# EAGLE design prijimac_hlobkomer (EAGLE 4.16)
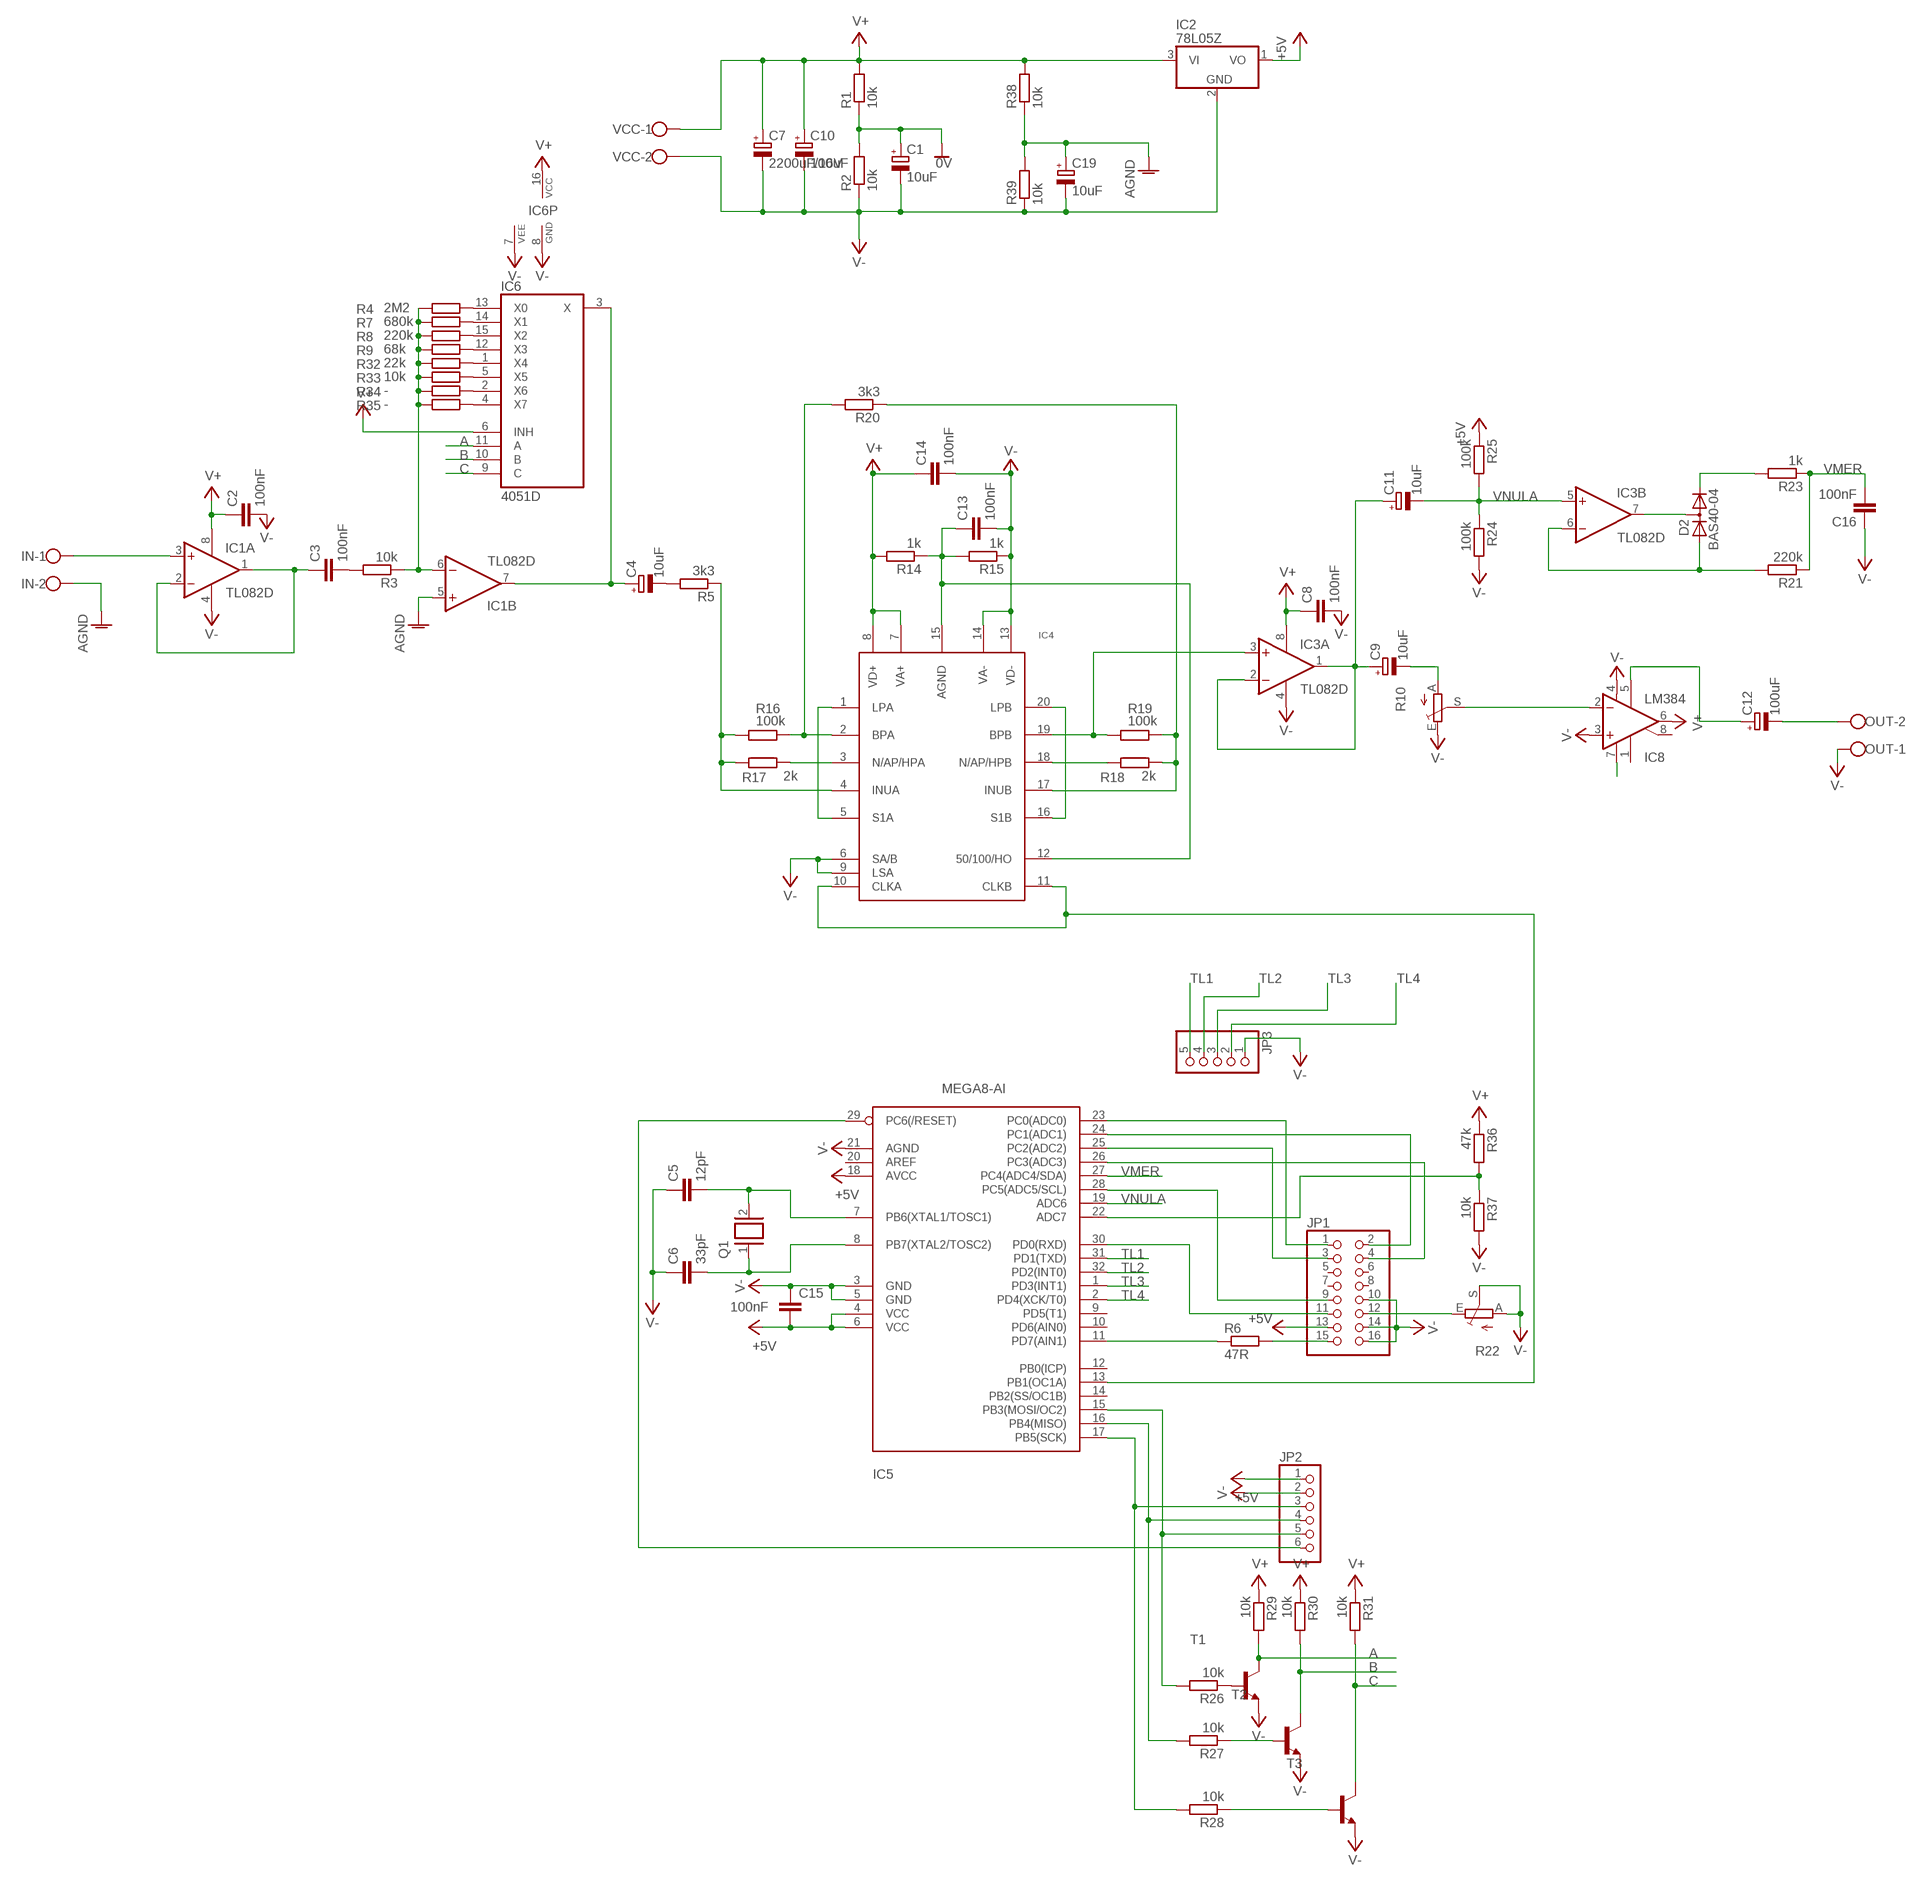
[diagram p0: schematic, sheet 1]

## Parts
C1  10uF  CPOL-EUE2.5-5  [E2,5-5]
C2  100nF  C-EUC0805K  [C0805K]
C3  100nF  C-EUC0805K  [C0805K]
C4  10uF  CPOL-EUE2.5-5  [E2,5-5]
C5  12pF  C-EUC0805K  [C0805K]
C6  33pF  C-EUC0805K  [C0805K]
C7  2200uF/16V  CPOL-EUE5-13  [E5-13]
C8  100nF  C-EUC0805K  [C0805K]
C9  10uF  CPOL-EUE2.5-5  [E2,5-5]
C10  100uF  CPOL-EUE2.5-5  [E2,5-5]
C11  10uF  CPOL-EUE2.5-5  [E2,5-5]
C12  100uF  CPOL-EUE2.5-5  [E2,5-5]
C13  100nF  C-EUC0805K  [C0805K]
C14  100nF  C-EUC0805K  [C0805K]
C15  100nF  C-EUC0805K  [C0805K]
C16  100nF  C-EUC0805K  [C0805K]
C19  10uF  CPOL-EUE2.5-5  [E2,5-5]
D2  BAS40-04  BAV199  [SOT23]
IC1  TL082D  [SO08]
IC2  78L05Z  [TO92]
IC3  TL082D  [SO08]
IC4  LTC1060DIL  [DIL20]
IC5  MEGA8-AI  [TQFP32-08]
IC6  4051D  [SO16]
IC8  LM384  NE5534N  [DIL08]
IN  W237-102  [W237-102]
JP1  PINHD-2X8  [2X08]
JP2  PINHD-1X6  [1X06]
JP3  PINHD-1X5  [1X05]
OUT  W237-102  [W237-102]
Q1  XTAL/S  [QS]
R1  10k  R-EU_R0805  [R0805]
R2  10k  R-EU_R0805  [R0805]
R3  10k  R-EU_R0805  [R0805]
R4  2M2  R-EU_R0805  [R0805]
R5  3k3  R-EU_R0805  [R0805]
R6  47R  R-EU_0207/7  [0207/7]
R7  680k  R-EU_R0805  [R0805]
R8  220k  R-EU_R0805  [R0805]
R9  68k  R-EU_R0805  [R0805]
R10  TRIM_EU-S64W  [S64W]
R14  1k  R-EU_R0805  [R0805]
R15  1k  R-EU_R0805  [R0805]
R16  100k  R-EU_R0805  [R0805]
R17  2k  R-EU_R0805  [R0805]
R18  2k  R-EU_R0805  [R0805]
R19  100k  R-EU_R0805  [R0805]
R20  3k3  R-EU_R0805  [R0805]
R21  220k  R-EU_R0805  [R0805]
R22  TRIM_EU-CA6V  [CA6V]
R23  1k  R-EU_R0805  [R0805]
R24  100k  R-EU_R0805  [R0805]
R25  100k  R-EU_R0805  [R0805]
R26  10k  R-EU_R0805  [R0805]
R27  10k  R-EU_R0805  [R0805]
R28  10k  R-EU_R0805  [R0805]
R29  10k  R-EU_R0805  [R0805]
R30  10k  R-EU_R0805  [R0805]
R31  10k  R-EU_R0805  [R0805]
R32  22k  R-EU_R0805  [R0805]
R33  10k  R-EU_R0805  [R0805]
R34  -  R-EU_R0805  [R0805]
R35  -  R-EU_R0805  [R0805]
R36  47k  R-EU_R0805  [R0805]
R37  10k  R-EU_R0805  [R0805]
R38  10k  R-EU_R0805  [R0805]
R39  10k  R-EU_R0805  [R0805]
T1  BC817-40-NPN-SOT23-BEC  [SOT23-BEC]
T2  BC817-40-NPN-SOT23-BEC  [SOT23-BEC]
T3  BC817-40-NPN-SOT23-BEC  [SOT23-BEC]
VCC  W237-102  [W237-102]

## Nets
0V: C1.+ R1.1 R2.2
+5V: C15.1 IC2.1(VO) IC5.4(VCC) IC5.6(VCC) IC5.18(AVCC) JP1.13 JP2.1 R25.1
A: IC6.11(A) R29.2 T1.C
AGND: C19.+ IC1.5(B:+IN) IN.2 R38.1 R39.2
B: IC6.10(B) R30.2 T2.C
B$1-0: IC5.23(PC0(ADC0)) JP1.1
B$1-1: IC5.24(PC1(ADC1)) JP1.2
B$1-2: IC5.25(PC2(ADC2)) JP1.3
B$1-3: IC5.26(PC3(ADC3)) JP1.4
C: IC6.9(C) R31.2 T3.C
N$1: C3.2 R3.2
N$2: C4.- R5.2
N$3: C6.2 IC5.8(PB7(XTAL2/TOSC2)) Q1.1
N$4: C3.1 IC1.1(A:OUT) IC1.2(A:-IN)
N$5: C5.2 IC5.7(PB6(XTAL1/TOSC1)) Q1.2
N$6: IC6.13(X0) R4.1
N$7: IC1.6(B:-IN) R3.1 R4.2 R7.2 R8.2 R9.2 R32.2 R33.2 R34.2 R35.2
N$8: C4.+ IC1.7(B:OUT) IC6.3(X)
N$9: IC6.14(X1) R7.1
N$10: IC5.30(PD0(RXD)) JP1.11
N$11: IC1.3(A:+IN) IN.1
N$12: IC6.15(X2) R8.1
N$13: C13.1 IC4.12(50/100/HO) IC4.15(AGND) R14.1 R15.2
N$14: C9.+ C11.+ IC3.1(A:OUT) IC3.2(A:-IN)
N$15: C9.- R10.A
N$16: IC8.7(V+)
N$18: IC8.2(-IN) R10.S
N$19: C12.+ IC8.5(CMP)
N$21: C12.- OUT.2
N$22: IC6.12(X3) R9.1
N$23: IC4.1(LPA) IC4.5(S1A)
N$24: IC4.16(S1B) IC4.20(LPB)
N$25: IC4.4(INUA) R5.1 R16.2 R17.2
N$26: IC4.3(N/AP/HPA) R17.1
N$27: IC4.2(BPA) R16.1 R20.2
N$28: IC3.3(A:+IN) IC4.19(BPB) R19.2
N$29: IC4.18(N/AP/HPB) R18.2
N$30: IC4.17(INUB) R18.1 R19.1 R20.1
N$31: JP1.15 R6.2
N$32: IC5.11(PD7(AIN1)) R6.1
N$33: IC4.10(CLKA) IC4.11(CLKB) IC5.13(PB1(OC1A))
N$34: IC5.28(PC5(ADC5/SCL)) JP1.9
N$35: IC5.29(PC6(/RESET)) JP2.6
N$36: IC5.17(PB5(SCK)) JP2.3 R28.2
N$37: IC5.16(PB4(MISO)) JP2.4 R27.2
N$38: IC5.15(PB3(MOSI/OC2)) JP2.5 R26.2
N$39: D2.3(AC) IC3.7(B:OUT)
N$40: D2.1(A) IC3.6(B:-IN) R21.2
N$41: IC5.22(ADC7) R36.2 R37.1
N$42: JP1.12 R22.E
N$43: D2.2(C) R23.2
N$45: R26.1 T1.B
N$46: R27.1 T2.B
N$47: R28.1 T3.B
N$51: IC6.1(X4) R32.1
N$52: IC6.5(X5) R33.1
N$53: IC6.2(X6) R34.1
N$54: IC6.4(X7) R35.1
TL1: IC5.31(PD1(TXD)) JP3.5
TL2: IC5.32(PD2(INT0)) JP3.4
TL3: IC5.1(PD3(INT1)) JP3.3
TL4: IC5.2(PD4(XCK/T0)) JP3.2
V+: C2.1 C7.+ C8.1 C10.+ C14.1 IC1.8(P:V+) IC2.3(VI) IC3.8(P:V+) IC4.7(VA+) IC4.8(VD+) IC6.6(INH) IC6.16(VCC) IC8.6(OUT) R1.2 R14.2 R29.1 R30.1 R31.1 R36.1 R38.2 VCC.1
V-: C1.- C2.2 C5.1 C6.1 C7.- C8.2 C10.- C13.2 C14.2 C15.2 C16.1 C19.- IC1.4(P:V-) IC2.2(GND) IC3.4(P:V-) IC4.6(SA/B) IC4.9(LSA) IC4.13(VD-) IC4.14(VA-) IC5.3(GND) IC5.5(GND) IC5.21(AGND) IC6.7(VEE) IC6.8(GND) IC8.3(+IN) IC8.4(V-) JP1.10 JP1.14 JP1.16 JP2.2 JP3.1 OUT.1 R2.1 R10.E R15.1 R22.A R22.S R24.2 R37.2 R39.1 T1.E T2.E T3.E VCC.2
VMER: C16.2 IC5.27(PC4(ADC4/SDA)) R21.1 R23.1
VNULA: C11.- IC3.5(B:+IN) IC5.19(ADC6) R24.1 R25.2
Unconnected: IC5.9(PD5(T1)) IC5.10(PD6(AIN0)) IC5.12(PB0(ICP)) IC5.14(PB2(SS/OC1B)) IC5.20(AREF) IC8.1(ON) IC8.8(ON/CMP) JP1.5 JP1.6 JP1.7 JP1.8

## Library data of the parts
C1 C4 C7 C9-C12 C19 = rcl:CPOL-EU: POLARIZED CAPACITOR, European symbol
C2 C3 C5 C6 C8 C13-C16 = rcl:C-EU: CAPACITOR, European symbol
D2 = diode:BAV199: DIODE low-leakage double diode
IC1 IC3 = linear:TL082: OP AMP
IC2 = linear:78*: Positive VOLTAGE REGULATOR Source: http://cache.national.com/ds/LM/LM78L05.pdf http://www.fairchildsemi.com/ds/LM/LM7805.pdf
IC4 = moje:LTC1060
IC5 = atmel:MEGA8: MICROCONTROLLER 8 Kbytes FLASH 1 kbytes SRAM 512 bytes EEPROM USART 6-channel 10 bit ADC 2-channel 8 bit ADC
IC6 = 40xx:4051: 8-channel ANALOG MULTIPLEXER
IC8 = linear:NE5534: AUDIO AMPLIFIER
IN OUT VCC = con-wago-500:W237-102: WAGO SCREW CLAMP
JP1 = pinhead:PINHD-2X8: PIN HEADER
JP2 = pinhead:PINHD-1X6: PIN HEADER
JP3 = pinhead:PINHD-1X5: PIN HEADER
Q1 = special:XTAL/S: CRYSTAL
R1-R9 R14-R21 R23-R39 = rcl:R-EU_: RESISTOR, European symbol
R10 R22 = pot:TRIM_EU-: POTENTIOMETER
T1-T3 = transistor:*-NPN-: NPN Transistror

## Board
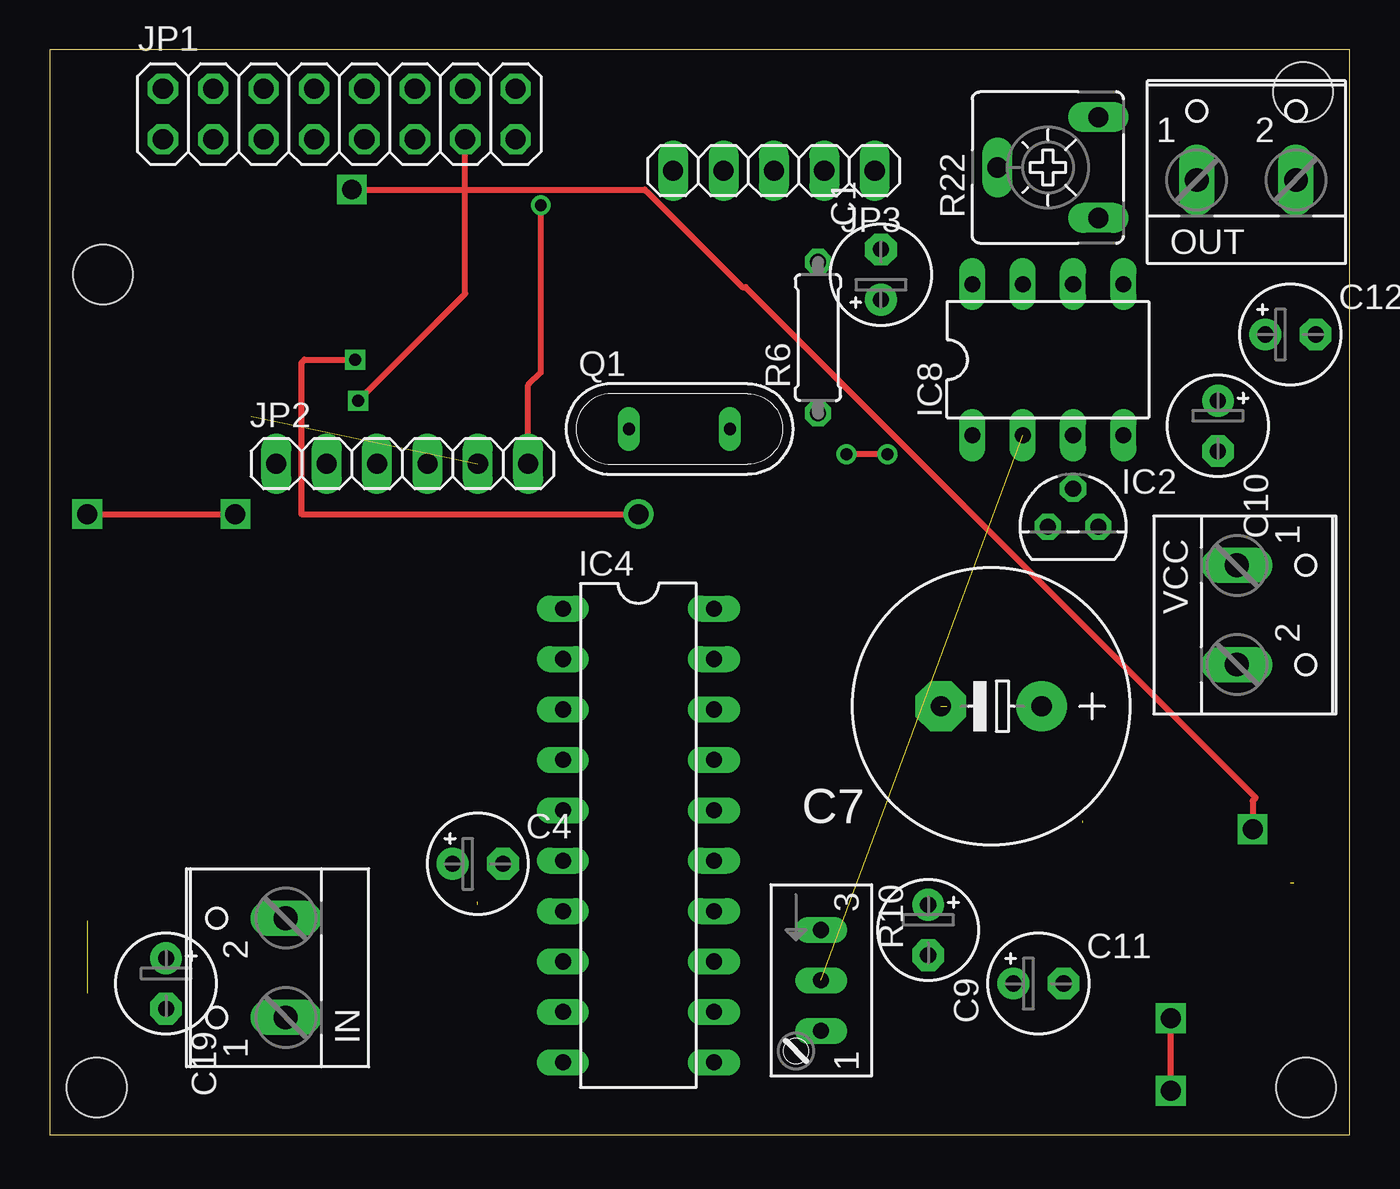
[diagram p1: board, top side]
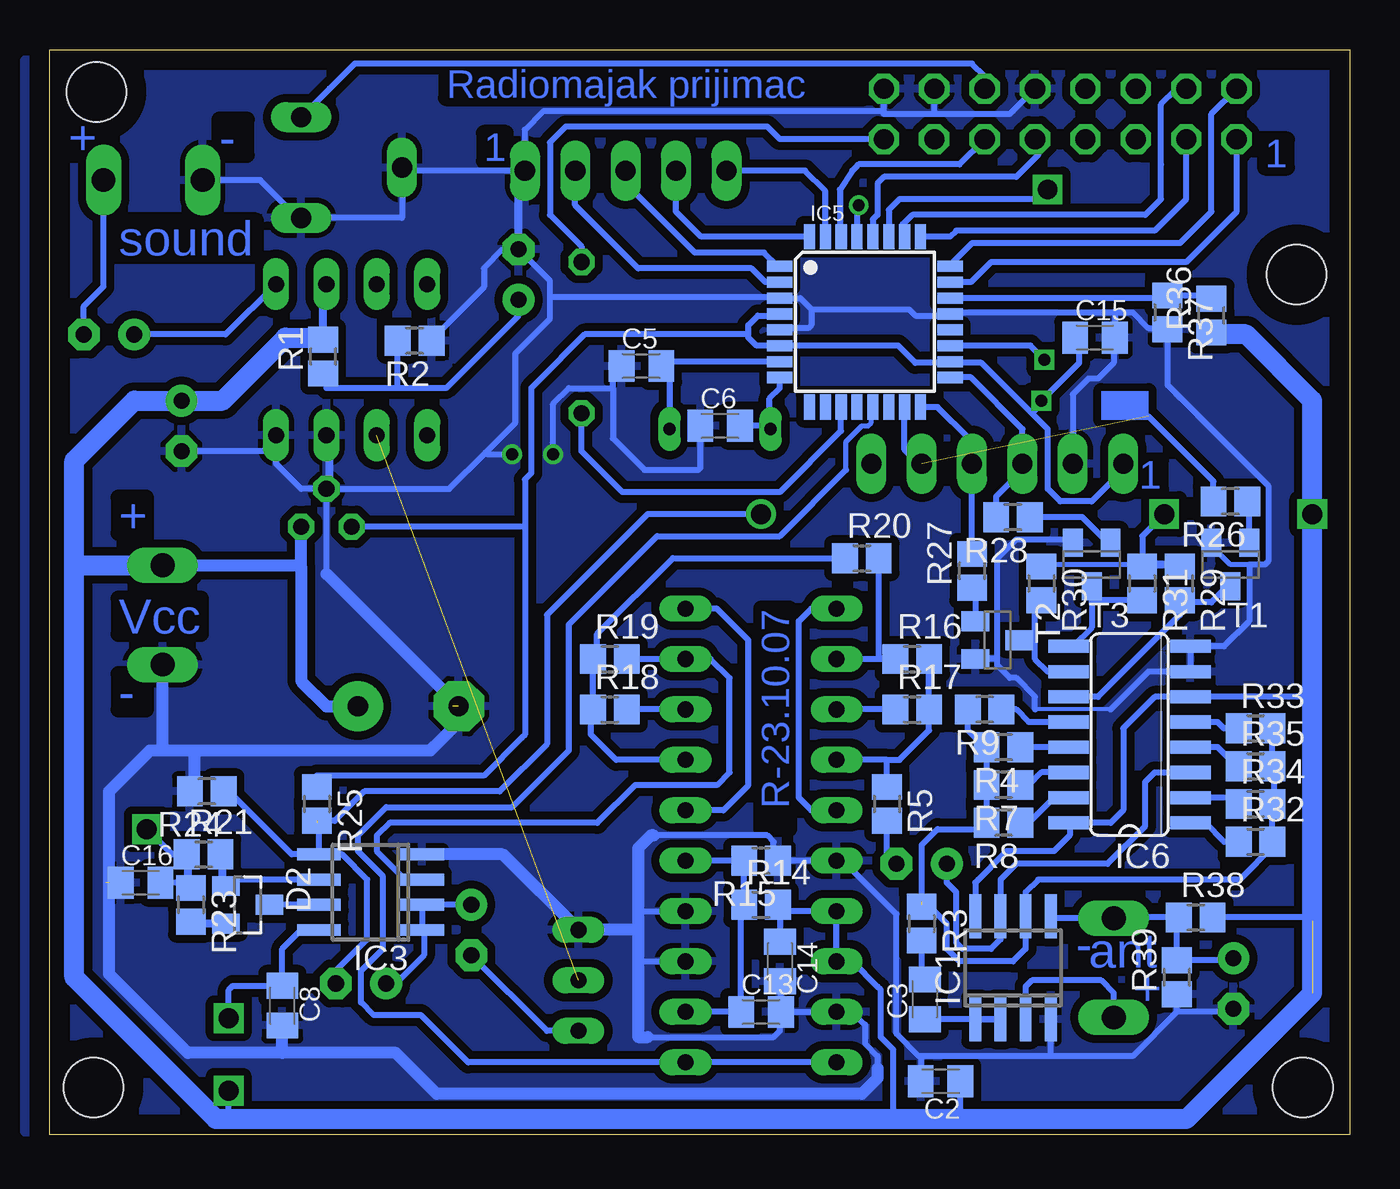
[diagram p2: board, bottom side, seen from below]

Size 65.54 x 54.67 mm. Coordinates in mm from the lower left corner, seen from the top.
Outline: 0,0 65.54,0 65.54,54.67 0,54.67 0,0
Copper layers (1*16): Top 0.035mm / dielectric 1.5mm / Bottom 0.035mm
Design rules "default": minimum track width 10mil, minimum drill 24mil, track to track 8mil, track to pad 8mil, pad to pad 8mil, via to via 8mil, smd to smd 8mil, copper to edge 40mil, drill to drill 8mil, minimum pad ring 10mil, minimum via ring 8mil, stop-mask expansion 4mil, vias tented up to drill 0mil, thermal gap 10mil
Holes 3 mm at 2.69,43.33 2.38,2.38 63.34,2.38 63.18,52.54

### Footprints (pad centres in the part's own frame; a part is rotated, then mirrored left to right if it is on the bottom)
E2,5-5 = drill 0.813 pad 1.6 round: + -1.27,0 | drill 0.813 pad 1.6 octagon: - 1.27,0
C0805K = smd 1.3 x 1.6: 1 -1,0; 2 1,0
E5-13 = drill 1.016 pad 2.54 round: + -2.54,0 | drill 1.016 pad 2.54 octagon: - 2.54,0
SOT23 = smd 1 x 1.4: 1 -0.95,-1.1; 2 0.95,-1.1; 3 0,1.1
SO08 = smd 0.6 x 2.2: 1 -1.905,-2.6; 2 -0.635,-2.6; 3 0.635,-2.6; 4 1.905,-2.6; 5 1.905,2.6; 6 0.635,2.6; 7 -0.635,2.6; 8 -1.905,2.6
TO92 = drill 0.813 octagon: 1 -1.27,0; 2 0,1.905; 3 1.27,0
DIL20 = drill 0.813 long: 1 -11.43,-3.81; 2 -8.89,-3.81; 3 -6.35,-3.81; 4 -3.81,-3.81; 5 -1.27,-3.81; 6 1.27,-3.81; 7 3.81,-3.81; 8 6.35,-3.81; 9 8.89,-3.81; 10 11.43,-3.81; 11 11.43,3.81; 12 8.89,3.81; 13 6.35,3.81; 14 3.81,3.81; 15 1.27,3.81; 16 -1.27,3.81; 17 -3.81,3.81; 18 -6.35,3.81; 19 -8.89,3.81; 20 -11.43,3.81
TQFP32-08 = smd 1.27 x 0.559: 1 -4.293,2.8; 2 -4.293,2; 3 -4.293,1.2; 4 -4.293,0.4; 5 -4.293,-0.4; 6 -4.293,-1.2; 7 -4.293,-2; 8 -4.293,-2.8; 17 4.293,-2.8; 18 4.293,-2; 19 4.293,-1.2; 20 4.293,-0.4; 21 4.293,0.4; 22 4.293,1.2; 23 4.293,2; 24 4.293,2.8 | smd 0.559 x 1.27: 9 -2.8,-4.293; 10 -2,-4.293; 11 -1.2,-4.293; 12 -0.4,-4.293; 13 0.4,-4.293; 14 1.2,-4.293; 15 2,-4.293; 16 2.8,-4.293; 25 2.8,4.293; 26 2,4.293; 27 1.2,4.293; 28 0.4,4.293; 29 -0.4,4.293; 30 -1.2,4.293; 31 -2,4.293; 32 -2.8,4.293
SO16 = smd 0.66 x 2.032: 1 -4.445,-3.073; 2 -3.175,-3.073; 3 -1.905,-3.073; 4 -0.635,-3.073; 5 0.635,-3.073; 6 1.905,-3.073; 7 3.175,-3.073; 8 4.445,-3.073; 9 4.445,3.073; 10 3.175,3.073; 11 1.905,3.073; 12 0.635,3.073; 13 -0.635,3.073; 14 -1.905,3.073; 15 -3.175,3.073; 16 -4.445,3.073
DIL08 = drill 0.813 long: 1 -3.81,-3.81; 2 -1.27,-3.81; 3 1.27,-3.81; 4 3.81,-3.81; 5 3.81,3.81; 6 1.27,3.81; 7 -1.27,3.81; 8 -3.81,3.81
W237-102 = drill 1.194 long: 1 -2.5,-1.27; 2 2.5,-1.27
2X08 = drill 1.016 octagon: 1 -8.89,-1.27; 2 -8.89,1.27; 3 -6.35,-1.27; 4 -6.35,1.27; 5 -3.81,-1.27; 6 -3.81,1.27; 7 -1.27,-1.27; 8 -1.27,1.27; 9 1.27,-1.27; 10 1.27,1.27; 11 3.81,-1.27; 12 3.81,1.27; 13 6.35,-1.27; 14 6.35,1.27; 15 8.89,-1.27; 16 8.89,1.27
1X06 = drill 1.016 long: 1 -6.35,0; 2 -3.81,0; 3 -1.27,0; 4 1.27,0; 5 3.81,0; 6 6.35,0
1X05 = drill 1.016 long: 1 -5.08,0; 2 -2.54,0; 3 0,0; 4 2.54,0; 5 5.08,0
QS = drill 0.61 long: 1 -2.54,0; 2 2.54,0
R0805 = smd 1.3 x 1.5: 1 -0.85,0; 2 0.85,0
0207/7 = drill 0.813 octagon: 1 -3.81,0; 2 3.81,0
S64W = drill 0.813 long: A 2.54,1.27; E -2.54,1.27; S 0,1.27
CA6V = drill 1.016 long: A -2.54,-2.54; E 2.54,-2.54; S 0,2.54
SOT23-BEC = smd 1 x 1.4: B -0.95,-1.1; C 0,1.1; E 0.95,-1.1

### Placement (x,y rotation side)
C1  41.9,43.33 90 top
C2  20.63,2.69 180 bottom
C3  21.43,6.82 90 bottom
C4  21.58,13.65 0 top
C5  35.71,38.73 0 bottom
C6  31.74,35.71 0 bottom
C7  47.46,21.59 180 top
C8  53.81,6.5 270 bottom
C9  44.29,10.31 270 top
C10  58.89,35.71 270 top
C11  49.84,7.61 0 top
C12  62.54,40.32 0 top
C13  29.68,6.19 0 bottom
C14  28.73,8.73 270 bottom
C15  12.85,40.16 0 bottom
C16  60.95,12.69 0 bottom
C19  5.87,7.61 270 top
D2  55.56,11.58 270 bottom
IC1  16.98,8.41 0 bottom
IC2  51.59,30.63 0 top
IC3  49.37,12.22 90 bottom
IC4  29.68,15.08 270 top
IC5  24.44,40.95 0 bottom
IC6  11.11,20.16 90 bottom
IC8  50.32,39.05 0 top
IN  10.63,8.41 90 top
JP1  14.6,51.43 0 top
JP2  17.77,33.81 0 top
JP3  36.51,48.57 180 top
OUT  60.32,49.37 0 top
Q1  31.74,35.56 0 top
R1  51.75,39.21 90 bottom
R2  47.14,40 180 bottom
R3  21.58,10.63 270 bottom
R4  17.46,19.52 180 bottom
R5  23.33,16.66 270 bottom
R6  38.73,40.16 90 top
R7  17.46,17.62 180 bottom
R8  17.46,15.71 180 bottom
R9  18.41,21.43 180 bottom
R10  37.62,7.77 270 top
R14  29.68,11.58 0 bottom
R15  29.68,13.81 180 bottom
R16  22.06,23.97 0 bottom
R17  22.06,21.43 0 bottom
R18  37.3,21.43 0 bottom
R19  37.3,23.97 0 bottom
R20  24.6,29.05 0 bottom
R21  57.78,14.12 0 bottom
R22  50.32,48.73 90 top
R23  58.41,11.58 270 bottom
R24  57.62,17.3 180 bottom
R25  52.06,16.66 270 bottom
R26  6.03,31.9 180 bottom
R27  19.04,28.41 90 bottom
R28  16.98,31.11 180 bottom
R29  8.57,27.78 270 bottom
R30  15.55,27.78 270 bottom
R31  10.47,27.78 270 bottom
R32  4.76,14.76 0 bottom
R33  4.76,20.47 0 bottom
R34  4.76,16.66 0 bottom
R35  4.76,18.57 0 bottom
R36  6.98,41.27 90 bottom
R37  9.2,41.43 270 bottom
R38  7.77,10.95 0 bottom
R39  8.73,7.93 90 bottom
T1  6.03,28.73 180 bottom
T2  17.77,24.92 270 bottom
T3  13.01,28.73 180 bottom
VCC  61.11,26.19 270 top

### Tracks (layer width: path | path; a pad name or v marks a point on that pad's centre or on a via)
0V
  Bottom 0.305: C1.+ 41.9,41.27 45.55,37.62 48.09,37.62 | 48.09,37.62 51.59,37.62 51.59,38.25 51.75,38.41 R1.1 | R2.2 47.99,37.72 48.09,37.62
+5V  (via drill 0.6)
  Top 0.305: JP1.13 20.95,42.38 v15.55,36.98
  Bottom 0.305: 20.31,38.89 21.9,38.89 22.77,39.75 28.66,39.75 28.73,39.68 28.73,39.69 IC5.6 29.91,39.75 30.32,40.16 30.32,40.32 | JP2.1 11.42,33.49 13.01,31.9 14.6,31.9 15.23,32.54 15.23,35.56 16.03,36.35 | 16.03,36.35 18.57,38.89 20.31,38.89 | 20.31,38.89 20.25,38.95 IC5.18 | R25.1 52.06,17.3 52.06,18.09 43.65,18.09 41.74,20 | 41.74,20 | 41.74,20 41.59,20.16 41.59,30.63 | 41.59,30.63 IC2.1 | 41.59,30.63 | 40.95,37.94 38.57,40.32 30.32,40.32 | 16.03,36.35 15.55,36.83 v15.55,36.98 13.65,38.89 13.65,40 13.81,40.16 C15.1 | 30.32,40.32 30.32,40.79 29.84,41.27 28.73,41.27 28.73,41.28 IC5.4 | 30.32,40.32 | 41.59,30.63 41.59,33.02 41.27,33.33 41.27,37.62 40.95,37.94 | 40.95,37.94
A
  Bottom 0.305: IC6.11 12.69,22.06 8.57,26.19 8.57,26.82 | 8.57,27.14 R29.2 8.57,26.82 | T1.C 6.17,27.63 6.98,26.82 8.57,26.82
AGND
  Bottom 0.305: 15.08,10.95 15.04,10.91 | C19.+ 5.97,8.78 R39.2 8.73,10.79 8.57,10.95 R38.1 11.9,10.95 IN.2 15.04,10.91 | 15.08,10.95 IC1.5 | 15.04,10.91 15.08,10.95
B
  Bottom 0.305: IC6.10 15.23,23.33 15.87,23.97 15.87,24.92 | R30.2 15.77,26.93 15.87,26.82 15.87,24.92 | 15.87,24.92 T2.C
B$1-0
  Bottom 0.305: IC5.23 19.11,42.95 18.09,43.97 8.25,43.97 5.71,46.51 5.71,49.68 5.87,49.84 5.71,50 JP1.1
B$1-1
  Bottom 0.305: JP1.2 6.98,51.43 6.98,46.51 8.57,44.92 19.04,44.92 20.16,43.81 20.15,43.8 IC5.24
B$1-2
  Bottom 0.305: IC5.25 20.15,45.25 19.84,45.56 9.84,45.56 8.25,47.14 8.25,50 8.41,50.16 JP1.3
B$1-3
  Bottom 0.305: JP1.4 8.73,52.7 9.52,51.91 9.52,48.89 | 10.31,46.35 22.06,46.35 22.54,45.87 22.54,45.24 22.53,45.25 IC5.26 | 10.31,46.35 | 10.31,46.35 9.52,47.14 9.52,48.89 | 9.52,48.89
C
  Bottom 0.305: IC6.9 13.96,24.6 13.01,25.55 13.01,26.82 | 13.01,26.82 T3.C | R31.2 12.91,26.93 13.01,26.82
N$1
  Bottom 0.305: 21.43,10 R3.2 21.58,8.09 21.43,7.93 C3.2
N$2
  Bottom 0.305: C4.- | R5.2 23.33,14.12 C4.-
N$3
  Bottom 0.305: 29.2,35.71 29.2,36.35 29.25,36.4 29.25,37.1 28.73,37.62 28.73,38.1 IC5.8 | Q1.1 29.2,35.71 | C6.2 29.2,35.71
N$4
  Bottom 0.305: IC1.1 18.89,5.87 18.82,5.81 IC1.2 21.37,5.81 21.43,5.87 C3.1
N$5
  Bottom 0.305: IC5.7 34.54,38.95 34.71,38.78 C5.2 34.44,38.73 34.28,38.89 Q1.2
N$6
  Bottom 0.305: IC6.13 R4.1
N$7  (1 unrouted)
  Bottom 0.305: R4.2 18.09,19.52 18.31,19.74 | R4.2 18.31,17.72 18.41,17.62 R7.2 18.31,15.61 | 18.31,15.61 R8.2 | 18.31,15.61 18.09,15.39 20.79,15.39 21.58,14.6 21.58,11.74 | 3.8,18.57 R35.2 | R33.2 3.91,18.67 3.8,18.57 | 3.8,18.57 3.8,16.66 R34.2 3.91,14.86 3.8,14.76 | 3.8,14.76 R32.2 4.12,14.76 | R4.2 18.41,19.52 19.26,20.37 R9.2 | 3.8,14.76 3.8,14.6 5.55,12.85 15.71,12.85 16.35,12.22 16.35,10.95 | 16.35,10.95 IC1.6 | R3.1 21.43,11.58 | 16.35,10.95 16.35,9.36 16.98,8.73 19.68,8.73 20.31,9.36 20.31,10.63 20.95,11.27 21.27,11.27 21.58,11.58 R3.1 | R3.1 21.16,11.48
N$8
  Bottom 0.305: IC6.3 9.84,18.25 10.31,17.78 10.31,15.55 12.22,13.65 16.82,13.65 17.62,12.85 IC1.7 17.62,9.84 18.09,9.36 19.52,9.36 19.84,9.68 19.84,12.22 20.31,12.7 C4.+
N$9
  Bottom 0.305: IC6.14 15.55,18.25 16.19,17.62 R7.1
N$10
  Bottom 0.305: IC5.30 25.71,45.25 25.71,45.24 25.71,47.62 25.08,48.57 | 25.08,48.57 | 24.92,48.73 25.08,48.57 | 24.92,48.73 | 24.92,48.73 24.76,48.89 19.68,48.89 JP1.11 | JP1.11
N$11
  Bottom 0.305: 16.35,5.87 IC1.3 16.35,7.46 16.03,7.77 12.54,7.77 11.9,7.14 IN.1 11.9,5.87
N$12
  Bottom 0.305: R8.1 16.19,15.71 14.92,16.98 IC6.15 13.96,16.98
N$13
  Bottom 0.305: R15.2 30.32,13.81 | R15.2 IC4.15 | R15.2 30.53,11.69 30.63,11.58 | C13.1 30.63,6.19 | C13.1 IC4.12 | 30.63,11.58 R14.1 | C13.1 30.68,11.54 30.63,11.58
N$14
  Bottom 0.305: C9.+ IC3.2 46.83,11.58 46.77,11.52 IC3.1 46.67,10.31 46.67,9.04 48.09,7.62 C11.+
N$15
  Bottom 0.305: R10.A 40.48,5.23 C9.-
N$18  (1 unrouted)
N$19
  Bottom 0.305: C12.+ 56.67,40.32 IC8.5
N$21
  Bottom 0.305: OUT.2 62.82,42.74 63.81,41.75 63.81,40.48 63.97,40.32 C12.-
N$22
  Bottom 0.305: IC6.12 16.19,20.79 16.82,21.43 R9.1 17.77,21.43
N$23
  Bottom 0.305: IC4.1 27.14,26.51 27.78,25.87 27.78,16.98 27.14,16.35 IC4.5
N$24
  Bottom 0.305: IC4.20 31.9,26.51 30.32,24.92 30.32,17.62 31.59,16.35 IC4.16
N$25
  Bottom 0.305: R16.2 21.21,21.53 21.11,21.43 R17.2 21.21,20.37 22.7,18.89 23.33,18.89 | 23.33,18.89 IC4.4 | R5.1 23.33,18.89
N$26
  Bottom 0.305: R17.1 IC4.3
N$27
  Bottom 0.305: 22.7,23.97 R16.1 23.65,23.97 | 23.65,23.97 IC4.2 | R20.2 23.75,24.07 23.65,23.97
N$28
  Bottom 0.305: 36.66,23.97 R19.2 IC4.19 32.22,23.97 31.27,23.01 31.27,18.25 31.9,17.62 36.03,17.62 37.94,15.71 48.41,15.71 49.05,15.08 49.05,14.28 47.62,12.85 IC3.3
N$29
  Bottom 0.305: IC4.18 R18.2
N$30
  Bottom 0.305: IC4.17 36.98,18.89 38.25,20.16 38.25,21.43 R18.1 38.15,23.86 38.25,23.97 | 38.25,23.97 R19.1 | 38.25,23.97 37.94,24.28 37.94,25.24 34.12,29.05 25.55,29.05 25.45,29.15 | 25.45,29.15 25.39,29.21 | 25.45,29.15 R20.1
N$31
  Bottom 0.305: R6.2 38.73,44.76 40.16,46.19 40.32,46.35 40.32,50 39.52,50.8 29.36,50.8 28.73,50.16 23.65,50.16 23.49,50 | JP1.15 | 23.49,50 | JP1.15 23.49,50
N$32
  Bottom 0.305: 28.73,32.38 36.66,32.38 38.73,34.44 R6.1 | IC5.11 25.64,35.47 28.73,32.38 | 28.73,32.38
N$33
  Bottom 0.254: 25.39,33.49 25.39,34.92 24.76,35.56 | 24.76,35.56 | 24.76,35.56 24.6,35.71 24.28,35.71 24.12,35.87 24.12,36.67 24.12,36.66 IC5.13
  Bottom 0.305: 24.12,36.83 24.04,36.74 IC5.13 | IC4.10 IC4.11 44.44,3.65 46.83,6.03 49.21,6.03 49.84,6.66 49.84,8.25 48.73,9.36 48.73,13.01 50,14.28 50,15.08 48.57,16.51 42.22,16.51 39.36,19.36 39.36,25.71 34.92,30.16 28.73,30.16 25.39,33.49
N$34
  Bottom 0.305: JP1.9 15.87,50 15.71,49.84 15.71,49.37 16.82,48.26 23.49,48.26 23.81,47.94 23.81,46.35 23.96,46.19 | IC5.28 24.04,46.12 23.96,46.19 | 23.96,46.19
N$35  (via drill 0.6)
  Top 0.305: v24.76,46.83 24.76,38.41 24.12,37.78 JP2.6
  Bottom 0.305: IC5.29 24.84,46.74 v24.76,46.83
N$36
  Bottom 0.305: IC5.17 19.1,38.15 16.5,35.56 JP2.3 16.5,33.49 16.66,33.33 | 16.66,33.33 | R28.2 17.83,32.17 16.66,33.33
N$37
  Bottom 0.305: IC5.16 20.78,36.66 19.2,35.08 19.2,33.49 JP2.4 19.04,29.36 19.15,29.26 | 19.15,29.26 19.2,29.21 | R27.2 19.15,29.26
N$38  (1 unrouted)
  Bottom 0.305: JP2.5 21.58,33.65 22.44,34.51 IC5.15 22.38,36.66 22.38,36.67 | R26.2 6.88,32.91 10.15,36.19
N$39
  Bottom 0.305: 54.6,11.58 D2.3 IC3.7
N$40
  Bottom 0.305: D2.1 56.19,12.53 56.19,12.85 IC3.6
  Bottom 0.406: D2.1 56.83,12.53 56.83,14.12 R21.2
N$41
  Bottom 0.305: 20.24,42.15 20.31,42.22 | 20.24,42.15 IC5.22 9.29,42.15 9.2,42.06 R37.1 7.04,42.28 6.88,42.12 | 20.24,42.15 20.21,42.12 | 6.88,42.12 6.82,42.06 | R36.2 6.88,42.12
N$42
  Bottom 0.305: 51.43,52.7 R22.E | JP1.12 18.41,53.34 19.04,53.97 50.16,53.97 51.43,52.7 | 51.43,52.7
N$43
  Bottom 0.406: 58.57,10.63 58.57,10.73 R23.2 | D2.2 58.57,10.63 | 58.57,10.63
N$45
  Bottom 0.305: 5.08,32.22 5.18,32.12 R26.1 | T1.B 5.08,32.22 | 5.08,32.22 5.07,32.22
N$46
  Bottom 0.305: R27.1 19.04,27.78 18.87,27.61 T2.B
N$47
  Bottom 0.305: T3.B 12.21,29.83 13.49,31.11 R28.1
N$51
  Bottom 0.305: IC6.1 7.3,15.71 6.34,14.76 R32.1 5.39,14.76
N$52
  Bottom 0.305: R33.1 6.34,20.47 6.66,20.79 IC6.5 8.25,20.79
N$53
  Bottom 0.305: 8.25,16.98 IC6.2 6.03,16.98 5.71,16.66 R34.1
N$54
  Bottom 0.305: IC6.4 6.66,19.52 5.71,18.57 R35.1
TL1
  Bottom 0.305: IC5.31 26.44,47.56 27.46,48.57 JP3.5 | JP3.5
TL2
  Bottom 0.305: IC5.32 32.7,45.25 33.97,46.51 JP3.4 33.97,48.73
TL3
  Bottom 0.305: JP3.3 36.51,47.94 33.01,44.45 29.52,44.45 28.83,43.75 IC5.1
TL4
  Bottom 0.305: IC5.2 29.46,42.95 30.16,43.65 35.87,43.65 39.05,46.83 JP3.2
V+  (via drill 1)  (1 unrouted)
  Top 0.305: v1.9,31.27 v9.36,31.27 | v56.51,2.22 v56.51,5.87
  Bottom 0.254: 15.55,28.73 | 15.55,28.73 R30.1 | 11.11,28.73 15.55,28.73
  Bottom 0.305: C14.1 28.73,11.58 R14.2 28.83,11.37 28.73,11.27 IC4.7 IC4.8 25.08,8.73 23.81,7.46 | 18.89,10.95 | IC3.8 52.22,10.31 | IC3.8 51.91,10.31 | IC3.8 52.86,10.31 53.81,9.36 C8.1 56.3,7.5 56.51,7.3 v56.51,5.87 | 7.93,22.06 | R29.1 8.57,28.41 | 8.57,28.41 8.78,28.63 | 11.11,28.73 11,28.63 R31.1 10.47,30.16 v9.36,31.27 | 15.55,28.73 R30.1 15.61,28.63 15.71,28.73 | 17.46,14.12 18.73,12.85 | 17.46,14.12 | 17.46,14.12 17.3,14.28 14.92,14.28 14.12,15.08 14.12,15.87 14.18,15.81 IC6.16 12.06,15.71 11.42,16.35 11.42,20.47 9.84,22.06 IC6.6 7.93,22.06 | 18.73,12.85 | 18.73,12.85 18.89,12.7 18.89,10.95 | 18.89,10.95 IC1.8 | R38.2 2.06,10.95 1.9,10.79 | 23.81,7.46 | 23.81,7.46 23.65,7.3 23.65,4.92 23.01,4.28 23.01,0.79 | C2.1 19.63,1.15 19.68,1.11 19.68,0.95 19.84,0.79 | 56.67,0.79 56.67,0.63 56.51,0.79 v56.51,2.22 | 1.9,22.06 7.93,22.06 | 8.57,28.41 8.73,28.41 9.04,28.73
  Bottom 0.406: 51.75,40.16 51.75,42.7 IC8.6 | R31.1 10.31,28.63 10.31,28.73 9.04,28.73
  Bottom 0.61: C7.+ 51.59,21.59 52.86,22.86 52.86,28.57 | IC2.3 | 52.86,28.57 IC2.3 | IC2.3 52.7,30.79 | VCC.1 52.98,28.69 52.86,28.57
  Bottom 1.016: VCC.1 64.25,28.69 64.29,28.73 | 64.29,28.73 64.29,7.93 57.14,0.79 56.67,0.79 56.51,0.79 23.01,0.79 19.84,0.79 8.25,0.79 1.9,7.14 1.9,22.06 v1.9,31.27 1.9,36.98 5.23,40.32 6.98,40.32 R36.1 | 64.29,28.73 64.29,33.97 61.27,36.98 C10.+ 56.83,36.98 53.65,40.16 51.75,40.16 R1.2
V-  (via drill 0.6)  (2 unrouted)
  Top 0.305: v42.22,34.29 v40.16,34.29
  Bottom 0.2: 12.06,21.43 15.87,21.43
  Bottom 0.254: 6.98,29.68 6.03,28.73 5.07,28.73
  Bottom 0.305: 35.08,15.08 29.36,15.08 29.05,14.76 29.05,13.81 R15.1 28.83,13.7 | C14.2 28.73,7.77 28.68,7.73 C13.2 | C13.2 IC4.9 25.08,6.19 24.44,5.55 24.44,4.6 23.81,3.96 23.81,3.33 | C13.2 28.73,6.19 28.73,5.23 29.05,4.92 35.4,4.92 | 15.08,5.87 IC1.4 15.08,3.96 | IC3.4 46.83,14.12 | 7.93,24.6 8.03,24.5 IC6.7 10.15,23.33 12.06,21.43 | 6.98,29.68 T1.E 6.98,29.68 | 7.93,24.6 IC6.8 | 7.93,24.6 6.34,24.6 5.07,25.87 5.07,28.73 4.28,28.73 4.12,28.89 4.12,32.7 8.73,37.3 | 17.77,23.97 17.78,23.97 T2.E 19.2,23.97 | 17.77,23.97 17.77,23.65 17.14,23.01 16.82,23.01 15.87,22.06 15.87,21.43 | 17.77,23.97 17.77,29.05 16.82,30 13.96,30 T3.E 13.96,29.84 | 20.31,41.27 20.23,41.35 IC5.21 | IC5.21 20.15,41.42 20.16,41.43 11.9,41.43 | IC5.21 20.24,41.35 20.31,41.43 20.47,41.27 21.9,41.27 | JP1.10 | 16.98,51.59 JP1.10 | 16.98,51.59 | 16.98,51.59 17.14,51.43 20.95,51.43 | 20.95,51.43 23.49,51.43 23.49,51.59 | 23.49,51.59 JP1.16 | 20.95,51.43 JP1.14 | IC2.2 51.75,32.54 | 47.78,48.57 | 47.78,48.57 R22.S 47.78,46.19 | 47.78,48.57 JP3.1 41.43,48.57 | 47.78,46.19 | 47.78,46.19 R22.A 52.86,46.03 | 47.78,46.19 | 51.75,32.54 IC2.2 | 51.75,32.54 51.79,32.59 | 41.43,48.57 | 41.43,48.57 41.59,48.73 41.59,50.64 40.63,51.59 23.49,51.59 | 15.08,3.96 10.95,3.96 8.73,6.19 | C19.- 6.03,6.35 6.18,6.19 8.73,6.19 | 8.73,6.19 R39.1 | 28.83,13.7 28.89,13.65 | 28.83,13.7 28.73,13.81 IC4.6 25.39,13.81 25.39,13.65 22.85,11.11 22.85,5.08 21.74,3.96 21.58,3.96 | 21.9,41.27 | 22.22,41.59 21.9,41.27 | IC2.2 51.59,28.25 51.59,28.09 | 62.54,17.3 62.66,17.3 | 62.54,17.3 | 52.86,46.03 | OUT.1 54.92,48.1 52.86,46.03 | 54.13,35.08 IC8.4 | C10.- 54.76,34.44 54.13,35.08 | 54.13,35.08 54.13,33.81 52.86,32.54 51.43,32.54
  Bottom 0.305: 51.43,32.54 IC2.2 | R2.1 46.29,40.06 43.65,42.7 43.65,43.65 42.7,44.6 C1.- | VCC.2 59.96,23.69 | R24.2 58.47,17.4 58.26,17.62 | 51.43,32.54 45.4,32.54 43.57,34.36 | 43.57,34.36 42.06,35.87 42.06,39.37 40.32,41.11 40.32,42.22 | 15.08,3.96 21.58,3.96 | C2.2 21.63,3.92 21.58,3.96 | 8.73,37.3 9.2,37.78 9.2,38.73 | 8.73,37.3 8.57,37.14 | 23.49,51.59 | 11.9,41.43 10.95,41.43 10.15,40.64 9.04,40.64 9.1,40.58 R37.2 9.2,38.73 | 9.2,38.73 | JP2.2 13.96,37.3 13.17,38.1 12.69,38.1 11.9,38.89 11.9,40 11.85,40.05 C15.2 11.85,41.38 11.9,41.43 | 27.14,41.59 27.71,42.15 IC5.3 28.66,42.15 | 27.14,41.59 27.14,40.79 27.3,40.64 28.41,40.64 28.57,40.48 28.64,40.55 IC5.5 | 22.22,41.59 | 27.14,41.59 22.22,41.59 | v40.16,34.29 40.16,36.83 39.36,37.62 37.14,37.62 | 43.57,34.36 43.49,34.29 v42.22,34.29 | C6.1 32.74,33.6 32.86,33.49 35.55,33.49 37.14,35.08 37.14,37.62 | 37.14,37.62 37.14,38.41 36.82,38.41 36.66,38.57 36.71,38.62 C5.1 | 28.66,42.15 28.57,42.06 | 28.66,42.15 28.73,42.22 40.32,42.22 | C1.- | 40.32,42.22 40.32,43.02 C1.- | 62.7,12.7 | 62.38,12.7 62.7,12.7 | 62.7,12.7 | 35.87,11.27 IC4.14 | 35.87,8.73 IC4.13
  Bottom 0.406: JP3.1 41.9,48.57 C1.- | IC2.2 51.43,32.54 51.43,35.24 IC8.3
  Bottom 0.61: 51.59,28.25 45.24,21.9 45.24,21.59 45.24,20.47 46.19,19.52 | 46.19,19.52 | 46.19,19.52 46.35,19.36 58.26,19.36 | 59.84,19.36 58.26,19.36 | 59.84,19.36 60.48,19.36 62.54,17.3 62.54,12.7 62.54,8.09 58.57,4.12 53.81,4.12 | 59.84,19.36 VCC.2 | 58.26,19.36 58.26,17.62 | C16.1 62.38,12.7 | 53.81,4.12 48.09,4.12 46.03,2.06 24.6,2.06 23.81,2.85 23.81,3.33 | 53.81,4.12 C8.2 | 35.4,4.92 35.87,4.92 35.87,8.73 35.87,10.31 | 35.08,15.08 35.24,15.08 35.87,14.44 35.87,11.27 35.87,10.31 | 35.87,10.31 R10.E 42.7,14.12 IC3.4
  pour Bottom (isolate 0.406): -0.48,55.4 -0.48,-0.8 -0.17,-1.12 65.56,-1.12 66.83,0.15 66.83,54.13 65.24,55.72 -0.17,55.72
VMER  (via drill 1)
  Top 0.305: 49.21,28.57 60.8,16.98 | 49.21,28.57 | 49.21,28.57 35.08,42.7 34.92,42.7 30.16,47.46 30,47.62 v15.23,47.62 | 60.8,16.98 | v60.64,15.39 60.64,16.82 60.8,16.98
  Bottom 0.305: R23.1 | C16.2 58.41,12.7 R23.1 | IC5.27 23.24,46.6 22.7,47.14 15.71,47.14 v15.23,47.62 | R21.1 59.37,14.12 v60.64,15.39
  Bottom 0.406: R21.1 58.57,14.12 58.57,12.43 R23.1
VNULA  (via drill 0.6, 1)  (1 unrouted)
  Top 0.305: v15.39,39.05 12.85,39.05 12.69,38.89 12.69,31.27 v29.68,31.27
  Bottom 0.305: R24.1 56.51,17.3 53.33,14.12 IC3.5 | IC3.5 51.97,15.61 52.06,15.71 | C11.- 51.11,8.25 49.52,9.84 49.52,12.85 50.79,14.12 IC3.5 | IC5.19 16.1,39.75 v15.39,39.05 | R25.2 51.17,15.81 49.68,17.3 42.86,17.3 40.48,19.68 40.48,26.19 35.4,31.27 v29.68,31.27
(copper drawn outside any net)
  shapes: Bottom area x1

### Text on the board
Bottom: Radiomajak prijimac | - | + | 1 | 1 | sound | 1 | + | R-23.10.07 | Vcc | - | ant | - | +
